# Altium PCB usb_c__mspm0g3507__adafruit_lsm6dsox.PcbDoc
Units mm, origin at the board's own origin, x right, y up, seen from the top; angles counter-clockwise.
Board outline 92 x 60 mm, 2 copper layers (Top, Bottom), stack 0 mm thick; 37 components, 30 nets, 196 pads, 69 vias.
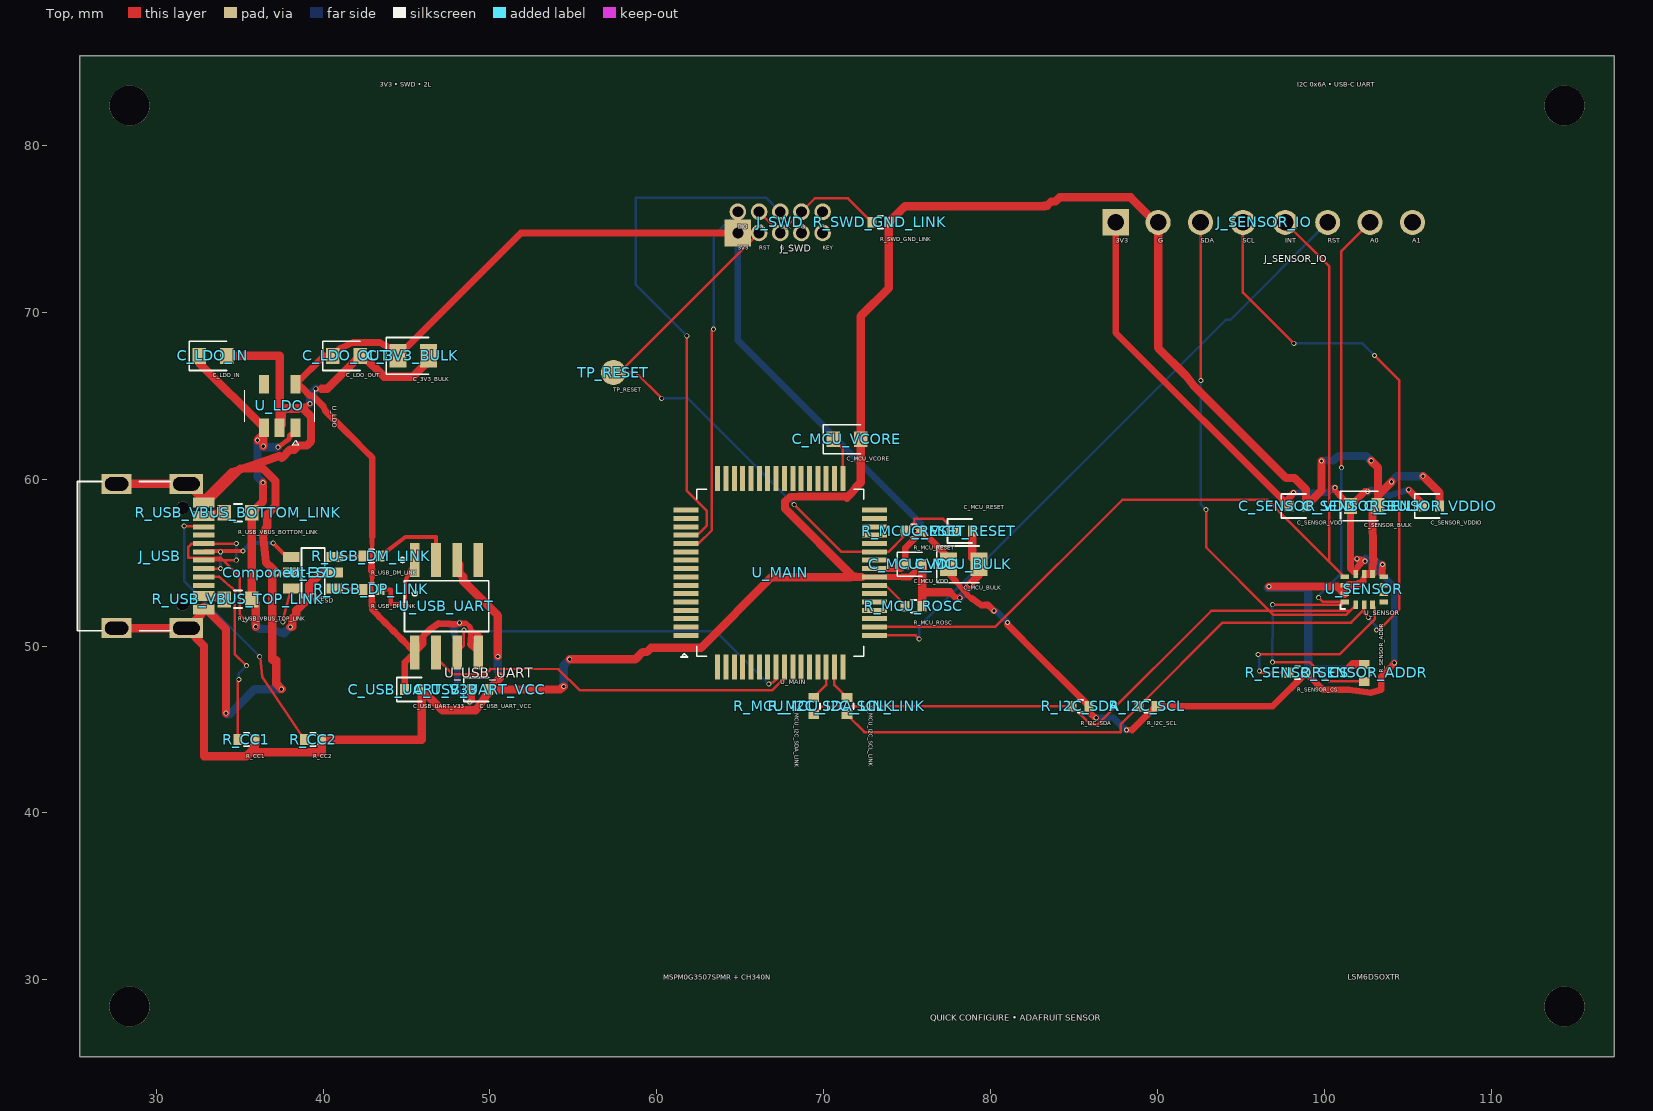
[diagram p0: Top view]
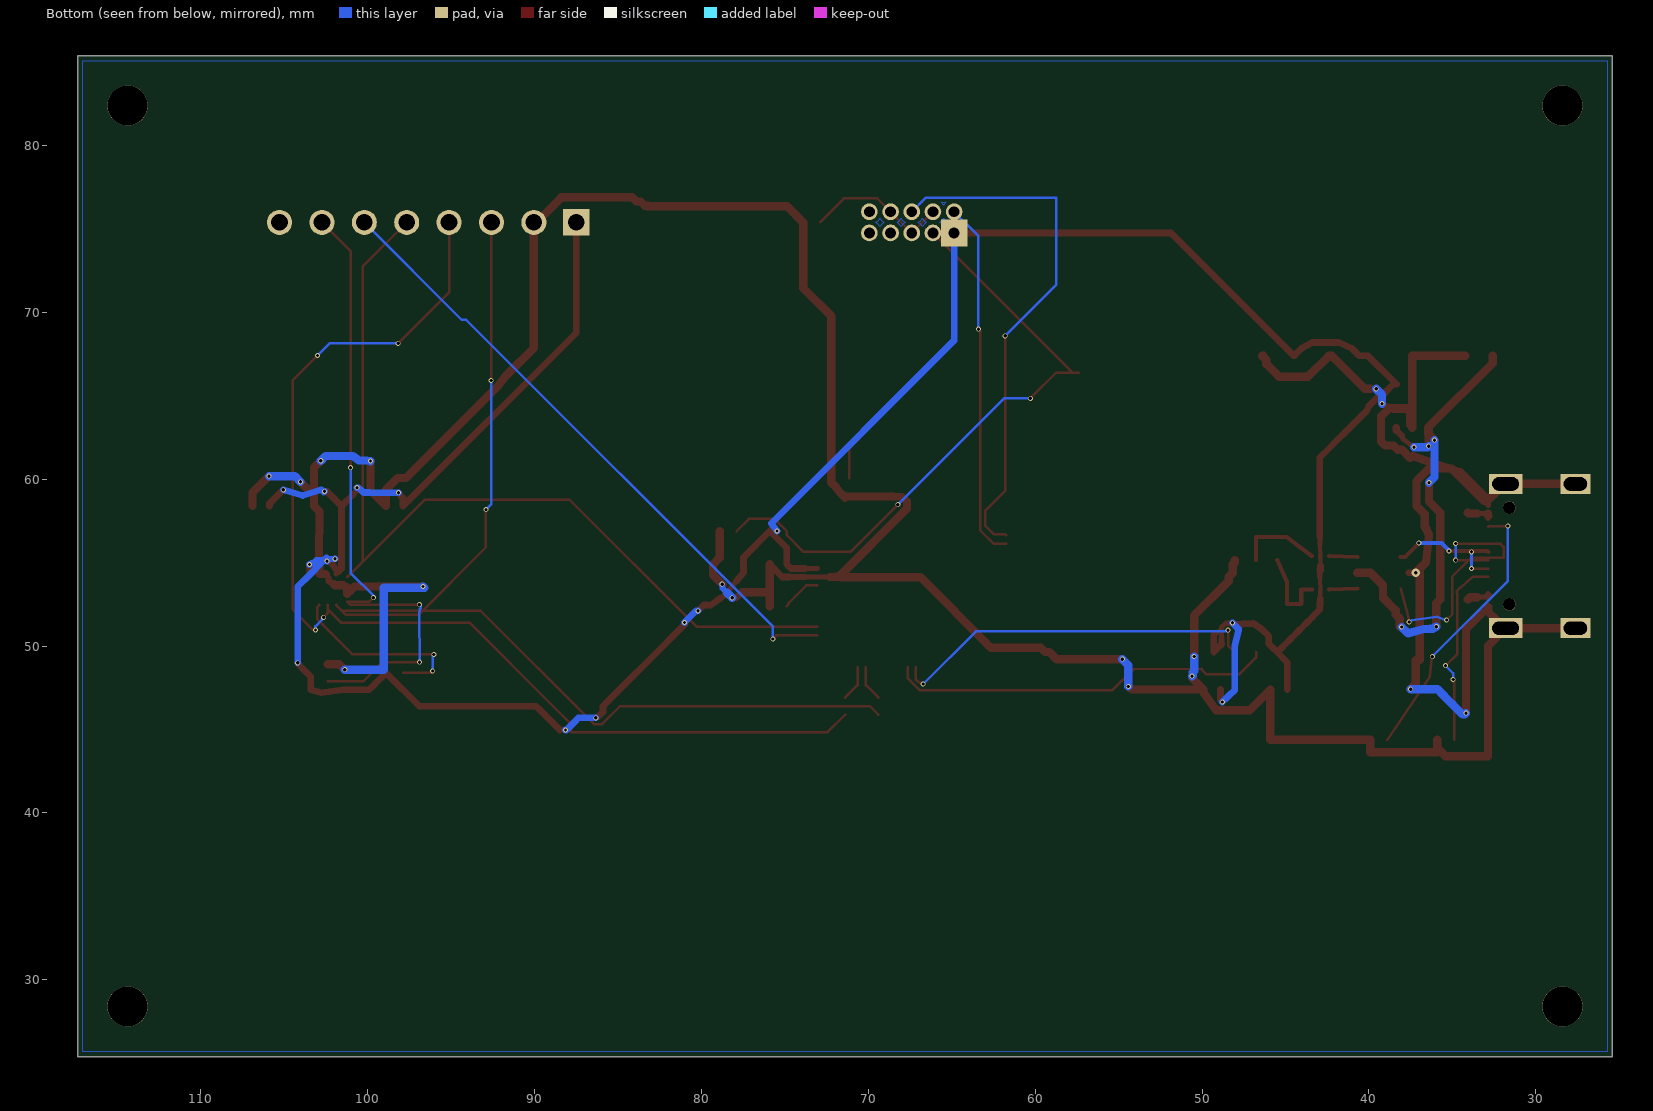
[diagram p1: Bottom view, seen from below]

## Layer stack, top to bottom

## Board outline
25.4,85.4 117.4,85.4 117.4,25.4 25.4,25.4

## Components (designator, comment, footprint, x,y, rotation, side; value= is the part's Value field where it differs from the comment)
C_3V3_BULK "" TSCIRCUIT-2.8500x1.4000mm 45.4,67.4 r0 top
C_LDO_IN "" TSCIRCUIT-2.4500x0.9500mm 33.4,67.4 r0 top
C_LDO_OUT "" TSCIRCUIT-2.4500x0.9500mm 41.4,67.4 r0 top
C_MCU_BULK "" TSCIRCUIT-2.8500x1.4000mm 78.4,54.9 r0 top
C_MCU_RESET "" TSCIRCUIT-1.5600x0.6400mm 78.4,56.9 r0 top
C_MCU_VCORE "" TSCIRCUIT-2.4500x0.9500mm 71.4,62.4 r0 top
C_MCU_VDD "" TSCIRCUIT-1.5600x0.6400mm 75.4,54.9 r0 top
C_SENSOR_BULK "" TSCIRCUIT-2.4500x0.9500mm 102.4,58.4 r0 top
C_SENSOR_VDD "" TSCIRCUIT-1.5600x0.6400mm 98.4,58.4 r0 top
C_SENSOR_VDDIO "" TSCIRCUIT-1.5600x0.6400mm 106.4,58.4 r0 top
C_USB_UART_V33 "" TSCIRCUIT-1.5600x0.6400mm 45.4,47.4 r0 top
C_USB_UART_VCC "" TSCIRCUIT-1.5600x0.6400mm 49.4,47.4 r0 top
Component-37 "" TSCIRCUIT-0.5000x0.5000mm 37.2,54.4 r0 top
J_SENSOR_IO "" TSCIRCUIT-19.2800x1.5000mm 96.4,75.4 r0 top
J_SWD "" TSCIRCUIT-6.0800x2.2700mm 67.4,75.4 r0 top
J_USB "" TSCIRCUIT-6.7732x9.8502mm 30.113,55.4 r90 top
R_CC1 "" TSCIRCUIT-1.5600x0.6400mm 35.4,44.4 r0 top
R_CC2 "" TSCIRCUIT-1.5600x0.6400mm 39.4,44.4 r0 top
R_I2C_SCL "" TSCIRCUIT-1.5600x0.6400mm 89.4,46.4 r0 top
R_I2C_SDA "" TSCIRCUIT-1.5600x0.6400mm 85.4,46.4 r0 top
R_MCU_I2C_SCL_LINK "" TSCIRCUIT-0.6400x1.5600mm 71.4,46.4 r270 top
R_MCU_I2C_SDA_LINK "" TSCIRCUIT-0.6400x1.5600mm 69.4,46.4 r270 top
R_MCU_RESET "" TSCIRCUIT-1.5600x0.6400mm 75.4,56.9 r0 top
R_MCU_ROSC "" TSCIRCUIT-1.5600x0.6400mm 75.4,52.4 r0 top
R_SENSOR_ADDR "" TSCIRCUIT-0.6400x1.5600mm 102.4,48.4 r90 top
R_SENSOR_CS "" TSCIRCUIT-1.5600x0.6400mm 98.4,48.4 r0 top
R_SWD_GND_LINK "" TSCIRCUIT-1.5600x0.6400mm 73.4,75.4 r0 top
R_USB_DM_LINK "" TSCIRCUIT-1.5600x0.6400mm 42.9,55.4 r0 top
R_USB_DP_LINK "" TSCIRCUIT-1.5600x0.6400mm 42.9,53.4 r0 top
R_USB_VBUS_BOTTOM_LINK "" TSCIRCUIT-2.4500x0.9500mm 34.9,58 r0 top
R_USB_VBUS_TOP_LINK "" TSCIRCUIT-2.4500x0.9500mm 34.9,52.8 r0 top
TP_RESET "" TSCIRCUIT-1.5000x1.5000mm 57.4,66.4 r0 top
U_ESD "" TSCIRCUIT-3.6000x2.5000mm 39.4,54.4 r0 top
U_LDO "" TSCIRCUIT-2.5000x3.7000mm 37.4,64.4 r270 top
U_MAIN "" TSCIRCUIT-12.8000x12.8000mm 67.4,54.4 r0 top
U_SENSOR "" TSCIRCUIT-2.8499x2.3500mm 102.4,53.4 r0 top
U_USB_UART "" TSCIRCUIT-4.3840x7.5712mm 47.4,52.4 r0 top

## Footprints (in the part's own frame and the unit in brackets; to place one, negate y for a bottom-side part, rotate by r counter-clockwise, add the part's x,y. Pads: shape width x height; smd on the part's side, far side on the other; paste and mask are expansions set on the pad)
TSCIRCUIT-0.5000x0.5000mm [mm]
TSCIRCUIT-0.6400x1.5600mm [mm]
  rect 0.54x0.64 smd: 1(-0.51,0) 2(0.51,0)
  silkscreen extent -0.15,-0.38 0.15,0.38
TSCIRCUIT-1.5000x1.5000mm [mm]
  round 1.5 smd: 1(0,0)
TSCIRCUIT-1.5600x0.6400mm [mm]
  rect 0.54x0.64 smd: 1(-0.51,0) 2(0.51,0)
  silkscreen extent -0.98,-0.72 0.51,0.72
TSCIRCUIT-2.4500x0.9500mm [mm]
  rect 0.8x0.95 smd: 1(-0.825,0) 2(0.825,0)
  silkscreen extent -1.42,-0.87 0.82,0.87
TSCIRCUIT-2.5000x3.7000mm [mm]
  rect 1.1x0.6 smd: 1(1.3,0.95) 2(1.3,0) 3(1.3,-0.95) 4(-1.3,-0.95) 5(-1.3,0.95)
  silkscreen extent -0.95,-2.1 2.35,2.1
TSCIRCUIT-2.8499x2.3500mm [mm]
  rect 0.5x0.28 smd: 1(-1.175,-0.75) 2(-1.175,-0.25) 3(-1.175,0.25) 4(-1.175,0.75) 8(1.175,0.75) 9(1.175,0.25) 10(1.175,-0.25) 11(1.175,-0.75)
  rect 0.28x0.5 smd: 5(-0.5,0.925) 6(0,0.925) 7(0.5,0.925) 12(0.5,-0.925) 13(0,-0.925) 14(-0.5,-0.925)
  silkscreen extent -1.42,-1.17 -1.14,-0.89
TSCIRCUIT-2.8500x1.4000mm [mm]
  rect 1.025x1.4 smd: 1(-0.913,0) 2(0.913,0)
  silkscreen extent -1.63,-1.1 0.91,1.1
TSCIRCUIT-3.6000x2.5000mm [mm]
  rect 1x0.6 smd: 1(-1.3,-0.95) 2(-1.3,0) 3(-1.3,0.95) 4(1.3,0.95) 5(1.3,0) 6(1.3,-0.95)
  silkscreen extent -0.7,-1.49 0.7,1.49
TSCIRCUIT-4.3840x7.5712mm [mm]
  rect 0.574x2.036 smd: 1(-1.905,2.768) 2(-0.635,2.768) 3(0.635,2.768) 4(1.905,2.768) 5(1.905,-2.768) 6(0.635,-2.768) 7(-0.635,-2.768) 8(-1.905,-2.768)
  silkscreen extent -2.79,-1.52 2.53,2.92
TSCIRCUIT-6.0800x2.2700mm [mm]
  rect 1.6x1.6 hole 0.65: 1(-2.54,-0.635)
  round 1 hole 0.65: 2(-2.54,0.635) 3(-1.27,0.635) 4(0,0.635) 5(1.27,0.635) 6(2.54,0.635) 7(2.54,-0.635) 8(1.27,-0.635) 9(0,-0.635) 10(-1.27,-0.635)
TSCIRCUIT-6.7732x9.8502mm [mm]
  rect 0.3x1.3 smd: 1(-3.35,-2.737) 2(-3.05,-2.737) 3(-2.55,-2.737) 4(-2.25,-2.737) 5(-1.75,-2.737) 6(-1.25,-2.737) 7(-0.75,-2.737) 8(-0.25,-2.737) 9(0.25,-2.737) 10(0.75,-2.737) 11(1.25,-2.737) 12(1.75,-2.737) 13(2.55,-2.737) 14(2.25,-2.737) 15(3.35,-2.737) 16(3.05,-2.737)
  rect 1.2x2 hole 0.8 slot 1.6 at 90 deg: 17(-4.325,-1.693) 18(4.325,-1.693)
  rect 1.2x1.8 hole 0.8 slot 1.4 at 90 deg: 19(4.325,2.487) 20(-4.325,2.487)
  round 0.75 hole 0.75 unplated: NPTH-1(-2.9,-1.468) NPTH-2(2.9,-1.468)
  silkscreen extent -4.47,-0.75 4.47,4.83
TSCIRCUIT-12.8000x12.8000mm [mm]
  rect 1.5x0.3 smd: 1(-5.65,-3.75) 2(-5.65,-3.25) 3(-5.65,-2.75) 4(-5.65,-2.25) 5(-5.65,-1.75) 6(-5.65,-1.25) 7(-5.65,-0.75) 8(-5.65,-0.25) 9(-5.65,0.25) 10(-5.65,0.75) 11(-5.65,1.25) 12(-5.65,1.75) 13(-5.65,2.25) 14(-5.65,2.75) 15(-5.65,3.25) 16(-5.65,3.75) 33(5.65,3.75) 34(5.65,3.25) 35(5.65,2.75) 36(5.65,2.25) 37(5.65,1.75) 38(5.65,1.25) 39(5.65,0.75) 40(5.65,0.25) 41(5.65,-0.25) 42(5.65,-0.75) 43(5.65,-1.25) 44(5.65,-1.75) 45(5.65,-2.25) 46(5.65,-2.75) 47(5.65,-3.25) 48(5.65,-3.75)
  rect 0.3x1.5 smd: 17(-3.75,5.65) 18(-3.25,5.65) 19(-2.75,5.65) 20(-2.25,5.65) 21(-1.75,5.65) 22(-1.25,5.65) 23(-0.75,5.65) 24(-0.25,5.65) 25(0.25,5.65) 26(0.75,5.65) 27(1.25,5.65) 28(1.75,5.65) 29(2.25,5.65) 30(2.75,5.65) 31(3.25,5.65) 32(3.75,5.65) 49(3.75,-5.65) 50(3.25,-5.65) 51(2.75,-5.65) 52(2.25,-5.65) 53(1.75,-5.65) 54(1.25,-5.65) 55(0.75,-5.65) 56(0.25,-5.65) 57(-0.25,-5.65) 58(-0.75,-5.65) 59(-1.25,-5.65) 60(-1.75,-5.65) 61(-2.25,-5.65) 62(-2.75,-5.65) 63(-3.25,-5.65) 64(-3.75,-5.65)
  silkscreen extent -5.95,-5.05 5,5
TSCIRCUIT-19.2800x1.5000mm [mm]
  rect 1.6x1.6 hole 1: 1(-8.89,0)
  round 1.5 hole 1: 2(-6.35,0) 3(-3.81,0) 4(-1.27,0) 5(1.27,0) 6(3.81,0) 7(6.35,0) 8(8.89,0)

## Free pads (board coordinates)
  round 2.4 hole 2.4 unplated: NPTH-3(28.4,28.4) NPTH-4(114.4,28.4) NPTH-5(28.4,82.4) NPTH-6(114.4,82.4)

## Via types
v1: diameter 0.3, hole 0.2, Top to Bottom, 68 vias
v2: diameter 0.5, hole 0.2, Top to Bottom, 1 vias

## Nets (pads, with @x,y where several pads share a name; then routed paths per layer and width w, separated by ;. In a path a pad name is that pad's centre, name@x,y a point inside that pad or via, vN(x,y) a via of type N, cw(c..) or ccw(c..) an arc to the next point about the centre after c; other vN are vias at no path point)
".J_SWD > .pin2 to .U_MAIN > .pin12": J_SWD.2 U_MAIN.12 | length 21.6
  Top w0.15: U_MAIN.12 62.499,56.15 63.298,56.949 63.298,59.12 63.298,68.898 v1(63.4,69)
  Bottom w0.15: v1(63.4,69) 63.4,69.14 63.4,74.575 J_SWD.2
".J_SWD > .pin4 to .U_MAIN > .pin13": J_SWD.4 U_MAIN.13 | length 31.9
  Top w0.15: U_MAIN.13 61.811,56.711 62.49,56.711 63.008,57.229 63.008,58.102 61.8,59.31 v1(61.8,68.6)
  Bottom w0.15: v1(61.8,68.6) 61.756,68.644 58.745,71.655 58.745,76.868 66.567,76.868 J_SWD.4
".U_MAIN > .pin42 to .R_MCU_ROSC > .pin1": R_MCU_ROSC.1 U_MAIN.42 | length 2.4
  Top w0.15: U_MAIN.42 73.719,53.65 74.769,52.6 74.769,52.521 R_MCU_ROSC.1
GND: C_3V3_BULK.2 C_LDO_IN.2 C_LDO_OUT.2 C_MCU_BULK.2 C_MCU_RESET.2 C_MCU_VCORE.2 C_MCU_VDD.2 C_SENSOR_BULK.2 C_SENSOR_VDD.2 C_SENSOR_VDDIO.2 C_USB_UART_V33.2 C_USB_UART_VCC.2 J_SENSOR_IO.2 J_USB.1 J_USB.2 J_USB.15 J_USB.16 J_USB.17 J_USB.18 J_USB.19 J_USB.20 R_CC1.2 R_CC2.2 R_MCU_ROSC.2 R_SENSOR_ADDR.2 R_SWD_GND_LINK.2 U_ESD.2 U_LDO.2 U_MAIN.41 U_SENSOR.2 U_SENSOR.3 U_SENSOR.6 U_SENSOR.7 U_USB_UART.3 | length 261.9
  Top w0.275: J_USB.2 J_USB.1@33.183,52.016
  Top w0.28: 101.085,53.29 U_SENSOR.2 ; U_SENSOR.3@101.225,53.51 U_SENSOR.3 101.475,53.65 ; U_SENSOR.6@102.363,54.075 U_SENSOR.6 U_SENSOR.6@102.54,54.325 ; U_SENSOR.7@102.894,54.575 102.894,54.331 U_SENSOR.7
  Top w0.3: J_USB.1@32.699,51.9 J_USB.1 J_USB.1@32.849,52.2 ; J_USB.15@32.699,58.9 J_USB.15 ; J_USB.16 J_USB.16@32.999,58.6 ; J_USB.16@32.849,58.6 J_USB.15 ; J_USB.15@32.999,58.9 J_USB.15 ; v1(39.568,65.421) 39.907,65.421 ; 72.3,54.133 72.552,54.133 73.033,54.133 U_MAIN.41 ; 72.3,54.15 72.303,54.15 72.677,54.15 U_MAIN.41 ; U_MAIN.41@73.8,54.15 73.706,54.15 73.612,54.15 73.519,54.15 73.425,54.15 73.331,54.15 73.237,54.15 73.144,54.15 U_MAIN.41
  Top w0.312: 38.513,64.225 38.866,64.38 v1(39.219,64.535)
  Top w0.325: J_USB.16 J_USB.16@32.849,58.6 ; J_USB.16@32.999,58.6 J_USB.15@33.124,58.725
  Top w0.375: U_MAIN.41@73.8,54.15 74.253,54.15 74.707,54.15 ; 102.337,53.9 U_SENSOR.6@102.363,54.075
  Top w0.4: 37.2,54.4 U_ESD.2@37.6,54.4 ; 74.707,54.15 75.16,54.15 75.41,54.4 75.66,54.65 C_MCU_VDD.2 ; 77.578,53.232 77.912,52.898 v1(78.16,52.898) ; 102.043,53.723 102.337,53.9
  Top w0.45: 67.681,58.681 68.025,58.963 68.507,58.963 ; 71.59,54.133 72.071,54.133 72.3,54.133 ; 102.888,54.825 102.932,54.933 102.964,55.08
  Top w0.475: 67.681,58.244 67.681,58.681 ; 68.507,58.963 68.989,58.963 69.471,58.963 69.954,58.963 70.436,58.963 70.918,58.963 71.4,58.963 ; 71.93,54.15 72.3,54.15 ; 102.888,54.825 102.893,54.7 102.894,54.575 ; 102.963,55.211 102.964,55.08
  Top w0.5: J_USB.20 J_USB.17 ; J_USB.19 J_USB.18 31.874,59.725 32.474,59.125 32.699,58.9 ; 32.699,51.9 32.474,51.675 31.874,51.075 J_USB.17 ; J_USB.1@32.849,52.2 J_USB.2 ; 32.999,58.9 33.182,59.083 33.515,59.416 33.848,59.749 34.181,60.082 34.514,60.415 37.4,61.4 37.525,61.275 38.025,61.775 38.275,61.775 38.525,62.025 39.025,62.025 39.275,62.275 39.275,63.775 38.775,64.275 37.775,64.275 37.525,64.025 37.525,63.275 37.4,63.15 U_LDO.2 ; J_USB.15@33.124,58.725 33.399,59 35.049,60.65 36.4,60.65 37.15,59.9 37.15,58.4 36.65,57.9 36.65,57.15 36.57,57.07 36.57,57.014 36.4,56.65 36.582,55.015 36.891,54.708 37.2,54.4 36.95,54.4 36.95,49.173 37.2,49.173 37.2,48.698 37.2,48.222 37.2,47.747 37.513,47.434 v1(37.499,47.419) ; J_USB.1@33.183,52.016 33.516,51.683 33.85,51.349 34.183,51.016 34.183,50.558 34.183,50.1 34.183,49.643 34.183,49.185 34.183,48.727 34.183,48.269 34.183,47.811 34.183,47.353 34.183,46.896 34.183,46.438 v1(34.183,45.98) ; C_LDO_IN.2 37.4,67.4 U_LDO.2 ; 38.513,64.225 37.4,64.225 U_LDO.2 ; 39.907,65.421 40.246,65.421 40.576,65.751 40.906,66.081 41.236,66.41 41.565,66.74 41.895,67.07 C_LDO_OUT.2 42.4,67.4 43.65,66.15 45.4,66.15 46.15,66.9 46.15,67.15 46.4,67.4 C_3V3_BULK.2 ; U_USB_UART.3 48.035,55.015 48.15,54.9 48.15,54.4 48.4,54.15 48.4,53.9 50.472,51.828 v1(50.472,49.381) ; v1(50.6,48.2) 50.6,48.09 50.255,47.745 C_USB_UART_VCC.2 ; v1(54.418,47.583) 54.378,47.543 54.351,47.543 54.208,47.4 53.731,47.4 53.253,47.4 52.776,47.4 52.298,47.4 51.82,47.4 51.343,47.4 50.865,47.4 50.388,47.4 C_USB_UART_VCC.2 ; v1(54.78,49.216) 55.253,49.216 55.726,49.216 56.199,49.216 56.672,49.216 57.146,49.216 57.619,49.216 58.092,49.216 58.565,49.216 58.716,49.216 59.15,49.65 59.4,49.65 59.65,49.9 62.65,49.9 66.883,54.133 70.627,54.133 71.108,54.133 71.59,54.133 ; 67.681,58.244 71.775,54.15 71.93,54.15 ; 71.4,58.963 71.4,58.9 71.65,59.15 71.918,59.502 72.225,59.808 72.225,60.24 72.225,60.672 72.225,61.104 72.225,61.536 72.225,61.968 C_MCU_VCORE.2 72.225,62.892 72.225,63.384 72.225,63.876 72.225,64.368 72.225,64.86 72.225,65.352 72.225,65.844 72.225,66.336 72.225,66.828 72.225,67.32 72.225,67.812 72.225,68.303 72.225,68.795 72.225,69.287 72.225,69.779 73.91,71.464 R_SWD_GND_LINK.2 74.232,75.722 74.554,76.044 74.876,76.366 74.951,76.366 75.438,76.366 75.925,76.366 76.413,76.366 76.9,76.366 77.387,76.366 77.875,76.366 78.362,76.366 78.849,76.366 79.337,76.366 79.824,76.366 80.311,76.366 80.799,76.366 81.286,76.366 81.773,76.366 82.261,76.366 82.748,76.366 83.235,76.366 83.202,76.4 83.4,76.4 83.65,76.65 83.9,76.65 84.15,76.9 88.4,76.9 89.9,75.4 J_SENSOR_IO.2 90.05,67.882 91.695,66.236 92.15,65.65 97.721,60.079 97.881,60.079 98.221,60.079 98.65,59.65 98.91,59.39 C_SENSOR_VDD.2 99.219,58.709 99.528,59.018 99.837,59.327 99.837,59.769 99.837,60.212 99.837,60.654 v1(99.837,61.096) ; R_MCU_ROSC.2 C_MCU_VDD.2 75.91,53.232 77.578,53.232 ; v1(78.766,53.713) 78.732,53.687 79.022,53.977 79.313,54.267 79.313,54.584 C_MCU_BULK.2 78.91,55.303 C_MCU_RESET.2 ; v1(96.695,53.579) 97.151,53.579 97.606,53.579 98.062,53.579 98.518,53.579 98.973,53.579 99.429,53.579 99.885,53.579 100.34,53.579 100.796,53.579 101.011,53.364 101.085,53.29 ; U_SENSOR.2 101.225,53.29 101.225,53.51 ; v1(101.38,48.588) 101.481,48.689 101.492,48.689 101.713,48.91 102.056,48.91 R_SENSOR_ADDR.2 ; 101.475,53.65 101.971,53.65 102.043,53.723 ; 102.54,54.325 102.76,54.325 U_SENSOR.7 ; v1(102.817,61.112) 103.225,60.705 C_SENSOR_BULK.2 ; 102.963,55.211 102.925,55.335 102.9,58.075 C_SENSOR_BULK.2 ; v1(104.035,59.851) 103.225,59.041 C_SENSOR_BULK.2 ; v1(105.921,60.187) 106.91,59.198 C_SENSOR_VDDIO.2 ; J_USB.17 32.863,50.017 32.864,43.4 35.4,43.4 35.9,43.9 35.9,44.15 35.91,44.16 R_CC1.2 35.91,43.65 39.91,43.65 R_CC2.2 40.41,44.4 40.91,44.4 45.91,44.4 C_USB_UART_V33.2 47.16,46.15 49.15,46.15 49.913,47.226 49.913,47.397 C_USB_UART_VCC.2
  Bottom w0.35: 78.457,53.193 78.736,53.472 v1(78.766,53.713)
  Bottom w0.5: v1(34.183,45.98) 34.258,45.905 34.378,45.905 34.681,46.208 34.983,46.51 35.286,46.813 35.589,47.116 35.892,47.419 36.294,47.419 36.695,47.419 37.097,47.419 v1(37.499,47.419) ; v1(39.219,64.535) 39.219,64.804 39.219,65.072 39.544,65.397 v1(39.568,65.421) ; v1(50.472,49.381) 50.472,48.948 50.472,48.514 50.565,48.421 50.565,48.235 v1(50.6,48.2) ; v1(54.418,47.583) 54.418,48.007 54.418,48.43 54.418,48.854 54.755,49.191 v1(54.78,49.216) ; v1(78.16,52.898) 78.177,52.915 78.179,52.915 78.457,53.193 ; v1(96.695,53.579) 96.607,53.491 99.044,53.491 99.044,48.588 99.511,48.588 99.978,48.588 100.445,48.588 100.913,48.588 v1(101.38,48.588) ; v1(99.837,61.096) 99.841,61.092 100.068,61.13 100.07,61.127 100.526,61.127 100.9,61.4 102.53,61.4 v1(102.817,61.112) ; v1(104.035,59.851) 104.371,60.187 v1(105.921,60.187)
MAIN_RESET: C_MCU_RESET.1 J_SWD.10 R_MCU_RESET.1 TP_RESET.1 U_MAIN.38 | length 38.5
  Top w0.15: v1(60.288,64.85) 60.277,64.861 58.738,66.4 TP_RESET.1 57.765,66.4 J_SWD.10 ; v1(68.231,58.48) 71.059,55.65 U_MAIN.38 73.889,55.65 74.889,56.651 R_MCU_RESET.1@74.889,56.899 ; R_MCU_RESET.1 75.442,57.452 75.442,57.636 77.166,57.628 C_MCU_RESET.1
  Bottom w0.15: v1(60.288,64.85) 61.859,64.85 68.171,58.538 v1(68.231,58.48)
MCU_I2C_SCL_LOCAL: R_MCU_I2C_SCL_LINK.1 U_MAIN.50 | length 2.2
  Top w0.15: U_MAIN.50 70.65,47.66 R_MCU_I2C_SCL_LINK.1
MCU_I2C_SDA_LOCAL: R_MCU_I2C_SDA_LINK.1 U_MAIN.51 | length 2.2
  Top w0.15: R_MCU_I2C_SDA_LINK.1 70.15,47.66 U_MAIN.51
MSPM0_VCORE: C_MCU_VCORE.1 U_MAIN.32 | length 2.6
  Top w0.15: C_MCU_VCORE.1 71.15,61.825 U_MAIN.32
SENSOR_ADDR0: J_SENSOR_IO.7 R_SENSOR_ADDR.1 U_SENSOR.1 | length 39.3
  Top w0.15: v1(96.9,49.044) 96.903,49.036 97.125,49.036 99.129,49.04 100.273,47.891 R_SENSOR_ADDR.1 ; v1(96.916,52.485) 101.06,52.485 U_SENSOR.1 99.925,52.65 v1(99.668,52.907) ; v1(101.038,60.696) 101.031,60.761 101.031,60.862 101.031,73.681 J_SENSOR_IO.7
  Bottom w0.15: v1(96.9,49.044) 96.922,51.927 96.895,52.215 96.84,52.27 96.84,52.409 v1(96.916,52.485) ; v1(99.668,52.907) 99.609,52.966 101.038,54.395 v1(101.038,60.696)
SENSOR_ADDR1: J_SENSOR_IO.8
SENSOR_CS: R_SENSOR_CS.1 U_SENSOR.12 | length 11.6
  Top w0.15: v1(96.042,49.501) 100.932,49.501 102.936,51.505 103.046,51.615 103.046,52.206 103.046,52.329 U_SENSOR.12 ; v1(96.112,48.513) 96.147,48.478 96.172,48.478 96.25,48.4 R_SENSOR_CS.1
  Bottom w0.15: v1(96.042,49.501) 96.046,49.497 96.046,49.485 96.112,49.419 v1(96.112,48.513)
SENSOR_INT: J_SENSOR_IO.5 U_MAIN.47 U_SENSOR.4 | length 56
  Top w0.15: U_MAIN.47 80.279,51.155 87.896,58.763 96.613,58.763 U_SENSOR.4 100.297,55.078 100.297,55.266 100.297,72.773 J_SENSOR_IO.5
SENSOR_RESET: J_SENSOR_IO.6 U_MAIN.48 | length 38
  Top w0.15: U_MAIN.48 75.511,50.65 75.715,50.446 v1(75.728,50.433)
  Bottom w0.15: v1(75.728,50.433) 75.728,51.179 94.115,69.566 94.376,69.566 J_SENSOR_IO.6
SENSOR_SCL: J_SENSOR_IO.4 R_I2C_SCL.1 R_MCU_I2C_SCL_LINK.2 U_SENSOR.13 | length 68.2
  Top w0.15: R_MCU_I2C_SCL_LINK.2 72.442,44.848 87.811,44.848 87.815,45.328 R_I2C_SCL.1 93.906,51.416 101.614,51.416 102.4,52.202 U_SENSOR.13 102.4,51.978 v1(102.648,51.73) ; J_SENSOR_IO.4 95.13,71.193 98.165,68.158 v1(98.178,68.145) ; v1(103.021,67.417) 104.513,65.925 104.513,52.214 103.276,50.977 103.149,50.977 v1(103.139,50.967)
  Bottom w0.15: v1(98.178,68.145) 102.287,68.145 102.916,67.516 102.922,67.516 v1(103.021,67.417) ; v1(102.648,51.73) 102.764,51.614 102.764,51.558 103.139,51.183 v1(103.139,50.967)
SENSOR_SDA: J_SENSOR_IO.3 R_I2C_SDA.1 R_MCU_I2C_SDA_LINK.2 U_SENSOR.14 | length 66.6
  Top w0.15: R_MCU_I2C_SDA_LINK.2 69.91,46.4 R_I2C_SDA.1 85.956,45.334 86.448,45.334 93.236,52.122 101.547,52.122 U_SENSOR.14 101.303,51.878 96.974,51.878 92.922,55.93 v1(92.922,58.177) ; J_SENSOR_IO.3 92.59,66.15 v1(92.605,65.924)
  Bottom w0.15: v1(92.605,65.924) 92.59,58.509 92.88,58.219 v1(92.922,58.177)
swd-ground-1-to-2: J_SWD.3 J_SWD.5 J_SWD.9 R_SWD_GND_LINK.1 | length 8.8
  Top w0.15: J_SWD.3 J_SWD.9 J_SWD.5 69.481,76.846 71.471,76.846 71.471,76.819 R_SWD_GND_LINK.1
UART_MSP_RX: U_MAIN.57 U_USB_UART.6 | length 22.4
  Top w0.15: U_USB_UART.6 48.443,50.04 v1(48.44,50.96) ; v1(66.712,47.735) 66.8,47.809 66.973,47.823 67.15,48 U_MAIN.57
  Bottom w0.15: v1(48.44,50.96) 48.519,50.916 48.519,50.888 63.559,50.888 v1(66.712,47.735)
UART_MSP_TX: U_MAIN.56 U_USB_UART.7 | length 23.3
  Top w0.15: U_USB_UART.7 46.765,49.314 47.776,48.303 49.738,48.303 50.044,48.609 50.025,48.65 54.12,48.609 55.369,47.361 66.932,47.361 67.064,47.493 67.65,48.079 U_MAIN.56
usb-dm-device: R_USB_DM_LINK.1 U_ESD.4 | length 1.7
  Top w0.25: U_ESD.4 R_USB_DM_LINK.1
usb-dm-port-tie: J_USB.7 J_USB.9 U_ESD.3 | length 8.9
  Top w0.15: J_USB.7 v1(33.85,54.65) ; J_USB.9 v1(33.85,55.65)
  Top w0.25: J_USB.9 32.899,55.7 v1(35.2,55.7) ; v1(37.009,56.183) 36.997,56.178 37.824,55.35 U_ESD.3
  Bottom w0.15: v1(33.85,54.65) v1(33.85,55.65)
  Bottom w0.25: v1(35.2,55.7) 35.2,55.745 35.638,56.183 v1(37.009,56.183)
usb-dm-uart: R_USB_DM_LINK.2 U_USB_UART.2 | length 5.1
  Top w0.25: R_USB_DM_LINK.2 44.95,56.55 46.765,56.55 U_USB_UART.2
usb-dp-device: R_USB_DP_LINK.1 U_ESD.6 | length 1.7
  Top w0.25: U_ESD.6 R_USB_DP_LINK.1
usb-dp-port-tie: J_USB.8 J_USB.10 U_ESD.1 | length 17.2
  Top w0.15: J_USB.8 v1(34.8,55.15) ; v1(34.8,56.15) J_USB.10 32.829,56.13 32.11,56.13 31.932,55.952 31.932,55.308 33.856,55.308 35.001,54.171 34.998,51.911 v1(35.337,51.567) ; v1(37.587,51.447) 37.632,51.784 U_ESD.1
  Bottom w0.15: v1(34.8,55.15) v1(34.8,56.15) ; v1(35.337,51.567) 35.338,51.566 35.42,51.566 35.912,51.77 37.434,51.566 v1(37.587,51.447)
usb-dp-uart: R_USB_DP_LINK.2 U_USB_UART.1 | length 5.1
  Top w0.25: R_USB_DP_LINK.2 44.05,53.4 44.05,52.53 44.9,52.53 44.9,53.85 U_USB_UART.1
USB_CC1: J_USB.6 R_CC1.1 | length 11.6
  Top w0.15: J_USB.6 33.782,54.15 34.499,53.527 34.548,53.498 34.735,53.281 34.7,53.09 34.7,49.53 v1(35.404,48.826) ; R_CC1.1 34.89,47.854 34.922,47.886 34.922,47.97 v1(34.952,48)
  Bottom w0.15: v1(34.952,48) 34.952,48.374 35.393,48.815 v1(35.404,48.826)
USB_CC2: J_USB.12 R_CC2.1 | length 16.7
  Top w0.15: v1(31.668,57.197) 32.802,57.197 J_USB.12 ; v1(36.201,49.369) 36.234,49.336 36.234,49.3 36.347,48.178 R_CC2.1
  Bottom w0.15: v1(31.668,57.197) 31.668,57.152 31.668,53.902 v1(36.201,49.369)
USB_VBUS_BOTTOM_LOCAL: J_USB.13 J_USB.14 R_USB_VBUS_BOTTOM_LINK.1 | length 1.5
  Top w0.3: J_USB.14 J_USB.14@32.849,57.8 ; J_USB.13 32.927,57.95 33.005,57.95 33.083,57.95 33.161,57.95 33.239,57.95 33.317,57.95 33.394,57.95 33.472,57.95 33.499,57.95
  Top w0.475: J_USB.13@32.849,57.8 J_USB.13 ; 33.499,57.95 R_USB_VBUS_BOTTOM_LINK.1@33.762,57.95
  Top w0.5: R_USB_VBUS_BOTTOM_LINK.1@33.762,57.95 34.025,57.95 R_USB_VBUS_BOTTOM_LINK.1
USB_VBUS_TOP_LOCAL: J_USB.3 J_USB.4 R_USB_VBUS_TOP_LINK.1 | length 1.6
  Top w0.3: J_USB.4 32.849,53 J_USB.3 32.944,52.958 33.032,52.939 33.499,52.939
  Top w0.5: 33.499,52.939 33.675,52.939 33.936,52.939 R_USB_VBUS_TOP_LINK.1
VBUS5: C_LDO_IN.1 R_USB_VBUS_BOTTOM_LINK.2 R_USB_VBUS_TOP_LINK.2 U_ESD.5 U_LDO.1 U_LDO.3 | length 29.4
  Top w0.312: v1(37.295,61.926) 37.408,61.989 37.685,62.21 37.962,62.431 38.037,62.619
  Top w0.375: 38.037,62.619 U_LDO.1@38.35,62.931
  Top w0.45: U_LDO.1@38.35,62.931 U_LDO.1
  Top w0.5: C_LDO_IN.1 32.575,66.975 U_LDO.3 ; v1(35.953,51.171) 35.953,51.638 35.953,52.105 35.953,52.572 R_USB_VBUS_TOP_LINK.2 R_USB_VBUS_BOTTOM_LINK.2 36.063,58.338 36.4,58.675 36.4,59.05 36.4,59.425 v1(36.4,59.8) ; v1(36.065,62.346) 36.45,62.731 U_LDO.3 ; v1(36.416,61.985) 36.416,63.066 U_LDO.3 ; v1(38.032,51.148) 38.034,51.15 38.15,51.15 38.15,51.65 38.4,51.9 38.4,52.15 39.15,52.9 39.15,53.65 39.9,54.4 U_ESD.5
  Bottom w0.5: v1(35.953,51.171) 36.009,51.115 36.096,51.115 36.166,51.046 36.317,51.038 36.715,51.032 37.65,50.775 v1(38.032,51.148) ; v1(36.065,62.346) 36.065,60.135 v1(36.4,59.8) ; v1(36.416,61.985) 36.474,61.926 v1(37.295,61.926)
VCC_3V3: C_3V3_BULK.1 C_LDO_OUT.1 C_MCU_BULK.1 C_MCU_VDD.1 C_SENSOR_BULK.1 C_SENSOR_VDD.1 C_SENSOR_VDDIO.1 C_USB_UART_V33.1 C_USB_UART_VCC.1 J_SENSOR_IO.1 J_SWD.1 R_I2C_SCL.2 R_I2C_SDA.2 R_MCU_RESET.2 R_SENSOR_CS.2 U_LDO.5 U_MAIN.40 U_SENSOR.5 U_SENSOR.8 U_USB_UART.5 U_USB_UART.8 | length 179.6
  Top w0.25: 42.905,54.813 42.909,55.101 42.914,55.389 42.9,55.525 42.921,55.846 42.942,56.167 ; 42.921,52.872 42.911,53.198 42.9,53.525 42.921,53.859 42.942,54.192 ; v1@48.275,51.337 48.65,51.337 48.831,51.042 49.089,50.795
  Top w0.275: v1(48.172,51.402) 48.375,51.395 48.578,51.387 48.845,51.134 48.84,50.793
  Top w0.28: U_SENSOR.5@101.76,54.465 U_SENSOR.5 U_SENSOR.5@101.85,54.5 ; U_SENSOR.8@103.487,54.29 U_SENSOR.8
  Top w0.288: 47.912,51.317 48.243,51.303 v1@48.275,51.337 ; 49.089,50.795 49.305,50.674
  Top w0.3: 42.942,56.167 42.942,56.562 ; v1(48.783,46.652) v1@48.8,46.687 ; 48.835,50.451 48.84,50.793 ; U_MAIN.40 73.15,54.65 73.25,54.65 73.35,54.65 73.45,54.65 73.55,54.65 73.65,54.65 73.75,54.65 U_MAIN.40@73.8,54.65 ; 77.924,53.887 78.149,53.611 78.4,53.3 78.6,53.1 ; U_SENSOR.5 101.85,54.5 102.017,54.753
  Top w0.312: 42.942,54.192 42.942,54.587
  Top w0.325: v1@81.016,51.294 v1(81.022,51.416) ; v1(88.152,44.978) 88.488,44.978
  Top w0.337: 78.6,53.1 78.6,53.06 78.885,52.859 ; 86.198,45.769 86.269,45.769 v1(86.333,45.705)
  Top w0.35: v1(100.648,59.501) 100.648,59.327 100.88,59.095 ; U_SENSOR.5@101.85,54.5 102.011,54.705 102.172,54.909 v1(102.444,55.097)
  Top w0.363: v1@48.8,46.687 48.89,46.777 ; 48.83,50.11 48.835,50.451
  Top w0.4: 42.905,54.813 42.9,54.525 42.942,54.587 ; 42.921,52.872 42.932,52.545 42.942,52.218 43.197,51.946 43.453,51.674 43.708,51.419 43.963,51.164 44.219,50.909 44.474,50.653 44.729,50.398 44.984,50.143 45.24,49.887 U_USB_UART.8 ; 42.942,56.562 42.942,56.957 42.942,57.351 42.942,57.746 42.942,58.141 42.942,58.536 42.942,58.931 42.942,59.326 42.942,59.721 42.942,60.116 42.942,60.51 42.942,60.905 42.942,61.3 42.824,61.418 42.556,61.686 42.289,61.953 42.021,62.221 41.754,62.489 41.486,62.756 41.218,63.024 40.951,63.291 40.683,63.559 40.416,63.827 40.148,64.094 40,64.4 39.4,65 39.2,65 38.81,65.432 38.542,65.7 U_LDO.5 40.05,67.4 C_LDO_OUT.1 40.795,67.622 41.016,67.843 41.8,68.2 43.4,68.2 44.047,67.841 44.267,67.62 C_3V3_BULK.1 51.853,74.765 J_SWD.1 ; C_USB_UART_V33.1 44.89,49.027 U_USB_UART.8 ; 47.912,51.317 47.582,51.33 47.251,51.344 46.921,51.357 46.4,51 46,50.6 45.998,50.135 45.746,49.883 U_USB_UART.8 ; 48.83,50.11 49.067,49.871 U_USB_UART.5 49.305,49.98 49.305,50.327 49.305,50.674 ; 48.89,46.777 48.89,47.089 C_USB_UART_VCC.1 ; U_MAIN.40@73.8,54.65 73.85,54.65 74.64,54.65 C_MCU_VDD.1 74.89,55.88 R_MCU_RESET.2 ; v1(75.475,56.9) 75.822,56.988 R_MCU_RESET.2 ; 77.924,53.887 77.698,54.163 77.473,54.438 77.48,54.669 C_MCU_BULK.1 77.488,55.323 R_MCU_RESET.2 ; 78.885,52.859 79.169,52.657 79.454,52.456 79.655,52.463 79.856,52.471 80.113,52.214 v1(80.21,52.117) ; v1@81.016,51.294 81.288,51.022 81.56,50.75 81.832,50.478 82.104,50.206 82.375,49.935 82.647,49.663 82.919,49.391 83.191,49.119 83.463,48.847 83.735,48.575 84.007,48.303 84.279,48.031 84.551,47.759 84.822,47.488 85.094,47.216 85.366,46.944 85.638,46.672 R_I2C_SDA.2 85.91,46.057 86.054,45.913 86.198,45.769 ; J_SENSOR_IO.1 87.51,68.78 C_SENSOR_VDD.1 97.89,58.637 97.89,58.875 98.085,59.069 98.085,59.121 v1(98.162,59.198) ; 88.488,44.978 88.725,45.215 88.962,45.452 89.199,45.689 89.436,45.926 89.673,46.163 R_I2C_SCL.2 96.91,46.4 R_SENSOR_CS.2 99.161,48.149 99.412,47.898 99.663,47.647 99.913,47.397 100.303,47.397 100.692,47.397 101.081,47.397 101.471,47.397 102.8,47.2 103.417,47.397 103.417,47.781 103.417,48.166 103.648,48.397 103.88,48.628 104.111,48.859 104.111,48.901 v1(104.21,49) ; 100.88,59.095 101.111,58.863 101.343,58.632 C_SENSOR_BULK.1 ; 101.76,54.465 101.575,54.65 C_SENSOR_BULK.1 ; v1(101.965,55.23) 102.326,55.148 102.185,55.007 102.017,54.753 ; v1(102.6,59.275) 102.45,59.275 C_SENSOR_BULK.1 ; U_SENSOR.8@103.487,54.29 103.465,54.324 v1(103.5,54.894) ; v1(105.066,59.368) 105.113,59.339 105.113,59.328 105.89,58.551 C_SENSOR_VDDIO.1
  Bottom w0.4: v1(48.172,51.402) 47.8,51 48.04,50.005 48.041,49.626 48.041,49.248 48.042,48.869 48.043,48.49 48.044,48.111 48.045,47.733 48.046,47.354 48.291,47.12 48.537,46.886 v1(48.783,46.652) ; J_SWD.1 64.86,68.322 75.822,57.361 v1(75.475,56.9) ; v1(80.21,52.117) 80.325,52.117 80.533,51.909 80.742,51.7 80.95,51.492 80.95,51.488 v1(81.022,51.416) ; v1(86.333,45.705) 86.68,45.705 87.027,45.705 87.374,45.705 87.617,45.463 87.859,45.22 88.101,44.978 v1(88.152,44.978) ; v1(98.162,59.198) 98.512,59.199 98.863,59.2 99.213,59.202 99.564,59.203 99.915,59.205 100.265,59.206 100.408,59.349 100.551,59.492 100.639,59.492 v1(100.648,59.501) ; v1(101.965,55.23) 103.061,55.158 103.255,54.964 103.35,54.964 v1(103.5,54.894) ; v1(102.444,55.097) 102.462,55.284 102.484,55.284 102.731,55.037 102.977,54.791 103.224,54.544 103.47,54.298 103.717,54.051 103.963,53.805 104.21,53.558 104.21,53.178 104.21,52.799 104.21,52.419 104.21,52.039 104.21,51.659 104.21,51.279 104.21,50.899 104.21,50.519 104.21,50.14 104.21,49.76 104.21,49.38 v1(104.21,49) ; v1(102.6,59.275) 102.647,59.228 102.805,59.38 103.906,59.029 v1(105.066,59.368)
pads on no net: J_SWD.6 J_SWD.7 J_SWD.8 J_USB.5 J_USB.11 J_USB.NPTH-1 J_USB.NPTH-2 U_LDO.4 U_MAIN.1 U_MAIN.2 U_MAIN.3 U_MAIN.4 U_MAIN.5 U_MAIN.6 U_MAIN.7 U_MAIN.8 U_MAIN.9 U_MAIN.10 U_MAIN.11 U_MAIN.14 U_MAIN.15 U_MAIN.16 U_MAIN.17 U_MAIN.18 U_MAIN.19 U_MAIN.20 U_MAIN.21 U_MAIN.22 U_MAIN.23 U_MAIN.24 U_MAIN.25 U_MAIN.26 U_MAIN.27 U_MAIN.28 U_MAIN.29 U_MAIN.30 U_MAIN.31 U_MAIN.33 U_MAIN.34 U_MAIN.35 U_MAIN.36 U_MAIN.37 U_MAIN.39 U_MAIN.43 U_MAIN.44 U_MAIN.45 U_MAIN.46 U_MAIN.49 U_MAIN.52 U_MAIN.53 U_MAIN.54 U_MAIN.55 U_MAIN.58 U_MAIN.59 U_MAIN.60 U_MAIN.61 U_MAIN.62 U_MAIN.63 U_MAIN.64 U_SENSOR.9 U_SENSOR.10 U_SENSOR.11 U_USB_UART.4
copper on no net:
  other v2: 37.2,54.4

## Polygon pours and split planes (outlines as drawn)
GND on Bottom (solid): 117.1,85.1 25.7,85.1 25.7,25.7 117.1,25.7
GND on Bottom (solid): 65.633,76.593 65.357,76.593 65.39,76.565 65.484,76.452 65.495,76.43 65.506,76.452 65.6,76.565
GND on Bottom (solid): 65.495,75.64 65.484,75.618 65.399,75.515 65.591,75.515 65.506,75.618
GND on Bottom (solid): 65.61,75.496 65.61,75.304 65.713,75.389 65.735,75.4 65.713,75.411
GND on Bottom (solid): 69.305,75.64 69.294,75.618 69.2,75.505 69.087,75.411 69.065,75.4 69.087,75.389 69.2,75.295 69.294,75.182 69.305,75.16 69.316,75.182 69.41,75.295 69.523,75.389 69.545,75.4 69.523,75.411 69.41,75.505 69.316,75.618
GND on Bottom (solid): 68.035,75.64 68.024,75.618 67.93,75.505 67.817,75.411 67.795,75.4 67.817,75.389 67.93,75.295 68.024,75.182 68.035,75.16 68.046,75.182 68.14,75.295 68.253,75.389 68.275,75.4 68.253,75.411 68.14,75.505 68.046,75.618
GND on Bottom (solid): 66.765,75.64 66.754,75.618 66.66,75.505 66.547,75.411 66.525,75.4 66.547,75.389 66.66,75.295 66.754,75.182 66.765,75.16 66.776,75.182 66.87,75.295 66.983,75.389 67.005,75.4 66.983,75.411 66.87,75.505 66.776,75.618

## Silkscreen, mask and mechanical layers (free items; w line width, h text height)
Top Overlay:
  text "3V3 • SWD • 2L" at 43.4,83.4 h0.48
  text "I2C 0x6A • USB-C UART" at 98.4,83.4 h0.5
  text "MSPM0G3507SPMR + CH340N" at 60.4,29.9 h0.52
  text "LSM6DSOXTR" at 101.4,29.9 h0.55
  text "QUICK CONFIGURE • ADAFRUIT SENSOR" at 76.4,27.4 h0.65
